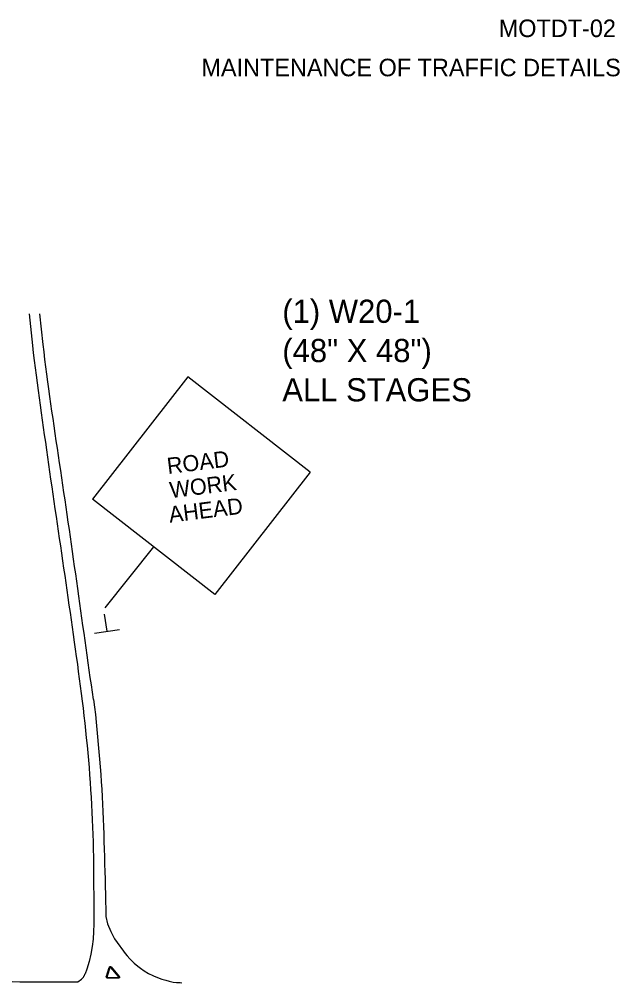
# Model space of a CAD drawing. Extents: x 1017892 to 1236694, y 658811 to 792468.
# Drawn here: x 1024005 to 1024407, y 660146 to 660790 of the extents above; entities that cross this region are included whole.
import ezdxf

# ---------------------------------------------------------------- set-up
doc = ezdxf.new("R2010")
doc.units = 0
for name, color, linetype in [('Level 3', 7, 'Continuous'), ('Level 8', 7, 'Continuous'), ('R_Border', 7, 'Continuous'), ('R_Proposed Road Annot', 7, 'Continuous'), ('S_CURB', 7, 'Continuous'), ('S_EDGE_PAVEMENT', 7, 'Continuous')]:
    doc.layers.add(name, color=color, linetype=linetype)

msp = doc.modelspace()

# ---------------------------------------------------------------- linework, layer by layer
at = {"layer": 'Level 3'}
for p, q in [((1024064.19, 660381.12), (1024062.52, 660392.52)), ((1024072.53, 660382.1), (1024055.83, 660379.65))]:
    msp.add_line(p, q, dxfattribs=at)
at = {"layer": 'Level 8'}
for p, q in [((1024118.16, 660551.16), (1024054.47, 660469.37)), ((1024199.95, 660487.47), (1024118.16, 660551.16)), ((1024199.95, 660487.47), (1024136.25, 660405.74)), ((1024136.25, 660405.74), (1024054.47, 660469.37))]:
    msp.add_line(p, q, dxfattribs=at)
at = {"layer": 'R_Proposed Road Annot'}
msp.add_line((1024062.92, 660396.73), (1024095.36, 660437.55), dxfattribs=at)
at = {"layer": 'S_CURB'}
msp.add_lwpolyline([(1024066.89, 660156.76), (1024072.34, 660150.32), (1024072.39, 660150.25), (1024072.43, 660150.18), (1024072.46, 660150.09), (1024072.48, 660150.01), (1024072.48, 660149.92), (1024072.48, 660149.83), (1024072.46, 660149.75), (1024072.43, 660149.67), (1024072.39, 660149.59), (1024072.34, 660149.52), (1024072.27, 660149.46), (1024072.2, 660149.41), (1024072.12, 660149.37), (1024072.04, 660149.34), (1024071.96, 660149.32), (1024071.87, 660149.31), (1024064.62, 660149.29), (1024064.52, 660149.3), (1024064.42, 660149.31), (1024064.31, 660149.34), (1024064.2, 660149.38), (1024064.1, 660149.44), (1024064, 660149.51), (1024063.91, 660149.6), (1024063.83, 660149.7), (1024063.76, 660149.8), (1024063.71, 660149.91), (1024063.67, 660150.03), (1024063.65, 660150.15), (1024063.64, 660150.26), (1024063.65, 660150.37), (1024063.66, 660150.48), (1024063.69, 660150.58), (1024065.64, 660156.52), (1024065.68, 660156.6), (1024065.73, 660156.69), (1024065.79, 660156.77), (1024065.85, 660156.83), (1024065.93, 660156.89), (1024066.02, 660156.94), (1024066.1, 660156.98), (1024066.19, 660157), (1024066.29, 660157.01), (1024066.38, 660157.01), (1024066.48, 660157), (1024066.57, 660156.97), (1024066.66, 660156.94), (1024066.75, 660156.89), (1024066.82, 660156.83)], close=True, dxfattribs=at)
for points in [[(1024066.07, 660156.26), (1024064.22, 660150.68)], [(1024066.07, 660156.26), (1024066.09, 660156.3), (1024066.11, 660156.33), (1024066.14, 660156.37), (1024066.17, 660156.4), (1024066.2, 660156.43), (1024066.24, 660156.45), (1024066.28, 660156.47), (1024066.32, 660156.48), (1024066.36, 660156.48), (1024066.41, 660156.48), (1024066.45, 660156.48), (1024066.49, 660156.46), (1024066.53, 660156.45), (1024066.57, 660156.42), (1024066.6, 660156.4), (1024066.63, 660156.37)], [(1024071.79, 660150.37), (1024066.63, 660156.37)], [(1024064.22, 660150.68), (1024064.2, 660150.61), (1024064.18, 660150.53), (1024064.18, 660150.45), (1024064.19, 660150.37), (1024064.2, 660150.28), (1024064.23, 660150.2), (1024064.27, 660150.11), (1024064.32, 660150.04), (1024064.37, 660149.97), (1024064.44, 660149.9), (1024064.51, 660149.85), (1024064.59, 660149.81), (1024064.67, 660149.78), (1024064.75, 660149.76), (1024064.82, 660149.74), (1024064.9, 660149.74)], [(1024064.9, 660149.74), (1024071.59, 660149.77)], [(1024071.59, 660149.77), (1024071.79, 660150.37)]]:
    msp.add_lwpolyline(points, dxfattribs=at)
at = {"layer": 'S_EDGE_PAVEMENT'}
for points in [[(1024012.06, 660593.26), (1024014.21, 660572.08), (1024014.8, 660567.11), (1024015.4, 660562.15), (1024015.99, 660557.18), (1024016.65, 660552.22), (1024017.31, 660547.26), (1024018.03, 660542.08), (1024018.71, 660537.13), (1024019.4, 660532.17), (1024020.08, 660527.22), (1024020.76, 660522.27), (1024021.45, 660517.32), (1024022.16, 660512.38), (1024022.87, 660507.43), (1024023.57, 660502.48), (1024024.28, 660497.54), (1024024.99, 660492.59), (1024025.7, 660487.65), (1024026.41, 660482.7), (1024027.13, 660477.76), (1024027.85, 660472.81), (1024028.57, 660467.84), (1024029.29, 660462.87), (1024030.01, 660457.93), (1024030.73, 660452.99), (1024031.45, 660448.05), (1024032.18, 660443.11), (1024032.91, 660438.17), (1024033.64, 660433.23), (1024034.37, 660428.29), (1024035.1, 660423.35), (1024035.83, 660418.41), (1024036.56, 660413.47), (1024037.27, 660408.53), (1024037.97, 660403.59), (1024038.67, 660398.64), (1024039.37, 660393.7), (1024040.08, 660388.76), (1024040.78, 660383.82), (1024041.48, 660378.88), (1024042.18, 660373.93), (1024042.87, 660369.11), (1024043.57, 660364.17), (1024044.27, 660359.23), (1024044.92, 660354.28), (1024045.57, 660349.33), (1024046.22, 660344.38), (1024046.87, 660339.43), (1024047.52, 660334.48)], [(1024055.05, 660335.42), (1024054.35, 660340.36), (1024053.65, 660345.31), (1024052.95, 660350.25), (1024052.25, 660355.19), (1024051.55, 660360.14), (1024050.85, 660365.08), (1024050.15, 660370.03), (1024049.44, 660375.02), (1024048.74, 660379.97), (1024048.04, 660384.91), (1024047.34, 660389.85), (1024046.64, 660394.79), (1024045.94, 660399.74), (1024045.24, 660404.68), (1024044.54, 660409.62), (1024043.84, 660414.57), (1024043.15, 660419.51), (1024042.45, 660424.46), (1024041.75, 660429.4), (1024041.05, 660434.34), (1024040.35, 660439.29), (1024039.65, 660444.23), (1024038.92, 660449.17), (1024038.2, 660454.12), (1024037.47, 660459.06), (1024036.74, 660464), (1024036.02, 660468.93), (1024035.3, 660473.85), (1024034.57, 660478.79), (1024033.85, 660483.73), (1024033.12, 660488.67), (1024032.39, 660493.62), (1024031.67, 660498.56), (1024030.94, 660503.51), (1024030.21, 660508.45), (1024029.49, 660513.39), (1024028.76, 660518.34), (1024028.04, 660523.28), (1024027.31, 660528.23), (1024026.58, 660533.17), (1024025.86, 660538.12), (1024025.2, 660543.08), (1024024.57, 660547.92), (1024023.91, 660552.88), (1024023.26, 660557.84), (1024022.61, 660562.8), (1024022.03, 660567.77), (1024021.46, 660572.74), (1024019.1, 660593.24)], [(1024047.52, 660334.48), (1024048.08, 660329.66), (1024048.66, 660324.7), (1024049.23, 660319.74), (1024049.76, 660314.77), (1024050.28, 660309.81), (1024050.75, 660304.83), (1024051.23, 660299.86), (1024051.7, 660294.89), (1024052.07, 660290.06), (1024052.44, 660285.13), (1024052.82, 660280.14), (1024053.12, 660275.16), (1024053.43, 660270.17), (1024053.7, 660265.18), (1024053.97, 660260.19), (1024054.19, 660255.2), (1024054.41, 660250.21), (1024054.64, 660245.22), (1024054.75, 660240.31), (1024054.87, 660235.39), (1024054.98, 660230.39), (1024055.1, 660225.4), (1024055.12, 660220.4), (1024055.15, 660215.4), (1024055.17, 660210.4), (1024055.19, 660205.4), (1024055.22, 660200.4), (1024055.24, 660195.4), (1024055.26, 660190.4), (1024055.21, 660185.4), (1024055.15, 660180.4), (1024054.81, 660175.39), (1024054.17, 660170.38), (1024053.31, 660165.37), (1024052.22, 660160.35)], [(1024055.05, 660335.42), (1024055.68, 660330.38), (1024056.31, 660325.43), (1024056.94, 660320.48), (1024057.39, 660315.5), (1024057.84, 660310.53), (1024058.29, 660305.55), (1024058.7, 660300.58), (1024059.11, 660295.6), (1024059.53, 660290.53), (1024059.89, 660285.51), (1024060.25, 660280.53), (1024060.61, 660275.54), (1024060.89, 660270.56), (1024061.17, 660265.57), (1024061.4, 660260.58), (1024061.62, 660255.58), (1024061.85, 660250.59), (1024061.96, 660245.6), (1024062.08, 660240.54), (1024062.19, 660235.5), (1024062.35, 660230.51), (1024062.51, 660225.51), (1024062.67, 660220.52), (1024062.79, 660215.52), (1024062.92, 660210.52), (1024063.02, 660205.52), (1024063.12, 660200.53), (1024063.23, 660195.53), (1024063.33, 660190.53), (1024064.35, 660185.55), (1024066.58, 660180.58), (1024069.21, 660175.63), (1024072.58, 660170.68)], [(1024072.58, 660170.68), (1024073.27, 660169.88), (1024075.03, 660167.39), (1024076.32, 660165.74), (1024077.62, 660164.12), (1024079.32, 660162.2), (1024080.74, 660160.81), (1024082.3, 660159.32), (1024084.78, 660157.2), (1024086.58, 660155.9), (1024088.99, 660154.14), (1024091.92, 660152.45), (1024094.86, 660151.03), (1024095.71, 660150.63), (1024100.7, 660148.73), (1024103.34, 660147.93), (1024105.69, 660147.37), (1024108.26, 660146.69), (1024110.68, 660146.5), (1024112.15, 660146.38), (1024112.95, 660146.33), (1024114.08, 660146.24)], [(1024052.22, 660160.35), (1024050.57, 660155.33)], [(1024050.57, 660155.33), (1024049.45, 660152.17)], [(1023943.5, 660147.39), (1023955.78, 660147.3), (1023960.78, 660147.26), (1023965.78, 660147.22), (1023970.78, 660147.19), (1023975.78, 660147.14), (1023980.78, 660147.09), (1023985.78, 660147.04), (1023990.78, 660147.03), (1023995.78, 660147), (1024000.78, 660146.97), (1024005.78, 660146.94), (1024010.78, 660146.89), (1024015.78, 660146.88), (1024020.78, 660146.87), (1024044.68, 660146.8)], [(1024044.68, 660146.8), (1024047.01, 660148.67), (1024047.25, 660148.88), (1024047.48, 660149.09), (1024047.71, 660149.32), (1024047.92, 660149.56), (1024048.12, 660149.8), (1024048.32, 660150.04), (1024048.5, 660150.3), (1024048.67, 660150.56), (1024048.83, 660150.82), (1024048.97, 660151.09), (1024049.11, 660151.35), (1024049.24, 660151.63), (1024049.35, 660151.9), (1024049.45, 660152.17)]]:
    msp.add_lwpolyline(points, dxfattribs=at)

# ---------------------------------------------------------------- texts
at = {"layer": 'Level 8'}
for s, p in [('(1) W20-1', (1024181.35, 660587.24)), ('(48" X 48")', (1024181.35, 660561.01)), ('ALL STAGES', (1024181.35, 660534.78))]:
    msp.add_text(s, height=15.5, dxfattribs=at).set_placement(p)
for s, rotation, p in [('ROAD', 7.09152, (1024104.91, 660486.16)), ('WORK', 7.09111, (1024106.7, 660470.06)), ('AHEAD', 7.09164, (1024106.09, 660453.67))]:
    msp.add_text(s, height=10.799, rotation=rotation, dxfattribs=at).set_placement(p)
at = {"layer": 'R_Border'}
for s, p in [('MOTDT-02', (1024326.06, 660778.24)), ('MAINTENANCE OF TRAFFIC DETAILS', (1024127.25, 660752.04))]:
    msp.add_text(s, height=11.724, dxfattribs=at).set_placement(p)

doc.saveas('drawing.dxf')
